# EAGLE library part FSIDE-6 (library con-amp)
AMP connector
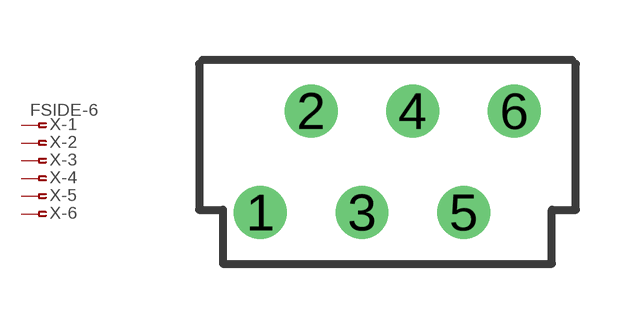
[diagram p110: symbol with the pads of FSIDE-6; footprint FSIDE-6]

Designator prefix X; gates -1=PIN-FV -2=PIN-F -3=PIN-F -4=PIN-F -5=PIN-F -6=PIN-F

## FSIDE-6 (OC_FARNELL: unknown; OC_NEWARK: unknown)  [FSIDE-6]
1  -1:1  pas
2  -2:1  pas
3  -3:1  pas
4  -4:1  pas
5  -5:1  pas
6  -6:1  pas

## Footprint FSIDE-6 (pad centres in mm)
AMP connector
drill 0.813 round: 1 -3.175,-1.27; 2 -1.905,1.27; 3 -0.635,-1.27; 4 0.635,1.27; 5 1.905,-1.27; 6 3.175,1.27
